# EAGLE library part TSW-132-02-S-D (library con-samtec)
THROUGH-HOLE .025" SQ POST HEADER Source: Samtec TSW.pdf
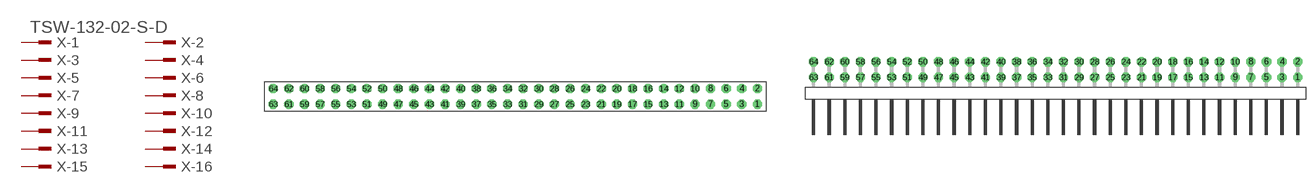
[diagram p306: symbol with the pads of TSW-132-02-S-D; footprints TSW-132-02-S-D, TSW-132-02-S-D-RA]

Designator prefix X; gates -1=MPINV -2=MPIN -3=MPIN -4=MPIN -5=MPIN -6=MPIN -7=MPIN -8=MPIN -9=MPIN -10=MPIN -11=MPIN -12=MPIN -13=MPIN -14=MPIN -15=MPIN -16=MPIN -17=MPIN -18=MPIN -19=MPIN -20=MPIN -21=MPIN -22=MPIN -23=MPIN -24=MPIN -25=MPIN -26=MPIN -27=MPIN -28=MPIN -29=MPIN -30=MPIN -31=MPIN -32=MPIN -33=MPIN -34=MPIN -35=MPIN -36=MPIN -37=MPIN -38=MPIN -39=MPIN -40=MPIN -41=MPIN -42=MPIN -43=MPIN -44=MPIN -45=MPIN -46=MPIN -47=MPIN -48=MPIN -49=MPIN -50=MPIN -51=MPIN -52=MPIN -53=MPIN -54=MPIN -55=MPIN -56=MPIN -57=MPIN -58=MPIN -59=MPIN -60=MPIN -61=MPIN -62=MPIN -63=MPIN -64=MPIN

## TSW-132-02-S-D (OC_FARNELL: unknown; OC_NEWARK: unknown)  [TSW-132-02-S-D]
1  -1:1  pas
2  -2:1  pas
3  -3:1  pas
4  -4:1  pas
5  -5:1  pas
6  -6:1  pas
7  -7:1  pas
8  -8:1  pas
9  -9:1  pas
10  -10:1  pas
11  -11:1  pas
12  -12:1  pas
13  -13:1  pas
14  -14:1  pas
15  -15:1  pas
16  -16:1  pas
17  -17:1  pas
18  -18:1  pas
19  -19:1  pas
20  -20:1  pas
21  -21:1  pas
22  -22:1  pas
23  -23:1  pas
24  -24:1  pas
25  -25:1  pas
26  -26:1  pas
27  -27:1  pas
28  -28:1  pas
29  -29:1  pas
30  -30:1  pas
31  -31:1  pas
32  -32:1  pas
33  -33:1  pas
34  -34:1  pas
35  -35:1  pas
36  -36:1  pas
37  -37:1  pas
38  -38:1  pas
39  -39:1  pas
40  -40:1  pas
41  -41:1  pas
42  -42:1  pas
43  -43:1  pas
44  -44:1  pas
45  -45:1  pas
46  -46:1  pas
47  -47:1  pas
48  -48:1  pas
49  -49:1  pas
50  -50:1  pas
51  -51:1  pas
52  -52:1  pas
53  -53:1  pas
54  -54:1  pas
55  -55:1  pas
56  -56:1  pas
57  -57:1  pas
58  -58:1  pas
59  -59:1  pas
60  -60:1  pas
61  -61:1  pas
62  -62:1  pas
63  -63:1  pas
64  -64:1  pas

## TSW-132-02-S-D-RA (OC_FARNELL: unknown; OC_NEWARK: unknown)  [TSW-132-02-S-D-RA]
Pads as for TSW-132-02-S-D

## Footprint TSW-132-02-S-D (pad centres in mm)
THROUGH-HOLE .025" SQ POST HEADER Source: Samtec TSW.pdf
drill 1 pad 1.5 octagon: 1 39.37,-1.27; 2 39.37,1.27; 3 36.83,-1.27; 4 36.83,1.27; 5 34.29,-1.27; 6 34.29,1.27; 7 31.75,-1.27; 8 31.75,1.27; 9 29.21,-1.27; 10 29.21,1.27; 11 26.67,-1.27; 12 26.67,1.27; 13 24.13,-1.27; 14 24.13,1.27; 15 21.59,-1.27; 16 21.59,1.27; 17 19.05,-1.27; 18 19.05,1.27; 19 16.51,-1.27; 20 16.51,1.27; 21 13.97,-1.27; 22 13.97,1.27; 23 11.43,-1.27; 24 11.43,1.27; 25 8.89,-1.27; 26 8.89,1.27; 27 6.35,-1.27; 28 6.35,1.27; 29 3.81,-1.27; 30 3.81,1.27; 31 1.27,-1.27; 32 1.27,1.27; 33 -1.27,-1.27; 34 -1.27,1.27; 35 -3.81,-1.27; 36 -3.81,1.27; 37 -6.35,-1.27; 38 -6.35,1.27; 39 -8.89,-1.27; 40 -8.89,1.27; 41 -11.43,-1.27; 42 -11.43,1.27; 43 -13.97,-1.27; 44 -13.97,1.27; 45 -16.51,-1.27; 46 -16.51,1.27; 47 -19.05,-1.27; 48 -19.05,1.27; 49 -21.59,-1.27; 50 -21.59,1.27; 51 -24.13,-1.27; 52 -24.13,1.27; 53 -26.67,-1.27; 54 -26.67,1.27; 55 -29.21,-1.27; 56 -29.21,1.27; 57 -31.75,-1.27; 58 -31.75,1.27; 59 -34.29,-1.27; 60 -34.29,1.27; 61 -36.83,-1.27; 62 -36.83,1.27; 63 -39.37,-1.27; 64 -39.37,1.27

## Footprint TSW-132-02-S-D-RA (pad centres in mm)
THROUGH-HOLE .025" SQ POST HEADER Source: Samtec TSW.pdf
drill 1 pad 1.5 octagon: 1 39.37,1.524; 2 39.37,4.064; 3 36.83,1.524; 4 36.83,4.064; 5 34.29,1.524; 6 34.29,4.064; 7 31.75,1.524; 8 31.75,4.064; 9 29.21,1.524; 10 29.21,4.064; 11 26.67,1.524; 12 26.67,4.064; 13 24.13,1.524; 14 24.13,4.064; 15 21.59,1.524; 16 21.59,4.064; 17 19.05,1.524; 18 19.05,4.064; 19 16.51,1.524; 20 16.51,4.064; 21 13.97,1.524; 22 13.97,4.064; 23 11.43,1.524; 24 11.43,4.064; 25 8.89,1.524; 26 8.89,4.064; 27 6.35,1.524; 28 6.35,4.064; 29 3.81,1.524; 30 3.81,4.064; 31 1.27,1.524; 32 1.27,4.064; 33 -1.27,1.524; 34 -1.27,4.064; 35 -3.81,1.524; 36 -3.81,4.064; 37 -6.35,1.524; 38 -6.35,4.064; 39 -8.89,1.524; 40 -8.89,4.064; 41 -11.43,1.524; 42 -11.43,4.064; 43 -13.97,1.524; 44 -13.97,4.064; 45 -16.51,1.524; 46 -16.51,4.064; 47 -19.05,1.524; 48 -19.05,4.064; 49 -21.59,1.524; 50 -21.59,4.064; 51 -24.13,1.524; 52 -24.13,4.064; 53 -26.67,1.524; 54 -26.67,4.064; 55 -29.21,1.524; 56 -29.21,4.064; 57 -31.75,1.524; 58 -31.75,4.064; 59 -34.29,1.524; 60 -34.29,4.064; 61 -36.83,1.524; 62 -36.83,4.064; 63 -39.37,1.524; 64 -39.37,4.064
